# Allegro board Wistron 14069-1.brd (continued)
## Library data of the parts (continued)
PT4702 PT4707-PT4709 PT4802 PT4807 PT5004 PT5101 PT5201 = ECAP-138D8-UH355: tolerance: 09.2771D.C8L
PU51 = DFN10G3-G265175H32: tolerance: 74.08068.A43
PU4002 PU4003 U401-U404 U3102 = SOT23DGS2D4H44: tolerance: 84.2N702.X31
PU4601 = WQFN56J6-G4D75H32: tolerance: 074.03607.0073
PU4701-PU4704 PU4708 PU4712 PU4718 PU4721 PU4802 PU4803 PU4807 PU4808 PU5003 PU5102 PU5203 PU5302 = PPAK-8PH48: tolerance: 084.04378.0037
PU4705-PU4707 PU4710 PU4711 PU4714 PU4715 PU4717 PU4801 PU4805 PU4806 PU4810 PU5001 PU5103 PU5201 PU5303 = PPAK-8PH48: tolerance: 084.04504.0037
PU4709 PU4713 PU4716 PU4719 PU4804 PU4809 = DFN8F3-G2416H32: tolerance: 074.09624.0BE3
PU5002 = QFN20-G1D75H32: tolerance: 74.08207.C73
PU5101 PU5301 = DFN10G3-G265175H32: tolerance: 74.08237.B73
PU5202 = QFN16G3-G1D85-UH40: tolerance: 74.05230.073
Q1 = SOT-363H44: tolerance: 75.27002.D7C
Q2 = SOT23DGS2D8H50: tolerance: 84.03418.A31
Q23 Q25 = SOT-363H44: tolerance: 84.2N702.A3F
Q58 Q5701 = SOT23DGS2D4H44: tolerance: 84.2N702.J31
Q72 Q5702 U2 = SOT-363H44: tolerance: 75.03904.A7C
Q73 Q3515 = SOT23CBE2D4H44: tolerance: 84.T3904.C11
Q98 Q3401 Q3402 Q3512 Q3514 Q3516 Q3518 Q4301-Q4304 Q6401 Q6406 Q6805 Q6807 U5202 U5203 = SOT23DGS2D4H48: tolerance: 84.2N702.E31
Q2002 Q2601 Q2606 Q2903 Q3107 = SOT23CBE2D4H44: tolerance: 84.T3904.H11
Q2004 Q2007 = SOT23DGS2D4H44: tolerance: 84.27002.Z31
Q2005 Q2602-Q2605 Q2702-Q2705 Q6403 Q6405 Q6407 Q6806 = SOT23CBE2D4H44: tolerance: 84.T3906.A11
Q2901 Q2902 Q3001-Q3003 = SC70-6H48: tolerance: 84.01C03.01F
Q3103 = SOT-363H44: tolerance: 75.03904.B7C
Q3106 Q3109 = SOT23DGS2D8H50: tolerance: 84.03419.031
Q3507 = SMD-TO-252-DGS6698H99: tolerance: 84.03004.036
Q3508 Q3509 = SOT23DGS2D8H50: tolerance: 84.03413.B31
Q5601 Q5602 = SOT23DGS2D4H44: tolerance: 84.2N702.031
Q5603 = SOT-363H44: tolerance: 75.27002.B7C; signal model: 6pins2
Q5703 Q6402 U5 U25-U28 = SOT-363H44: tolerance: 75.27002.F7C
Q5704 = SOT-363H44: tolerance: 75.27002.F7C; signal model: 6pins2
Q5705 = SOT23DGS2D4H48: tolerance: 84.02130.031
Q6404 = SOT23DGS2D4H44: tolerance: 84.00138.F31
Q9303 U3402 = SOIC8H79: tolerance: 75.05003.071
R78 R531 R3158 = R402H16: tolerance: 63.47334.1DL
R80 R4308-R4310 R6824 R6825 = R805H24: tolerance: 63.22133.16L
R83 R2054 R2203 R2205 R2207 R2210 R2212 R2214 R2217 R2219 R2221 R2223 R2602 R2611 R2612 R2618 R2622 R2630 R2632 R2932 R2941 R2942 R2944 R5707 R6408 R6414 R6416 R6420 R6421 R6823 R7919 = R402H16: tolerance: 63.47234.1DL
R302 R703 R1123 R1207 = R402H16: tolerance: 64.24R95.6DL
R403 R407 R408 R2038 R2040 R2043 = R402H16: tolerance: 64.51R05.6DL
R404 R405 = R402H16: tolerance: 63.51034.1DL
R414 R416-R420 R423-R432 R458 R813 R814 R879 R1605 R1606 R1706 R1707 R2010 R2019 R2021 R2030 R2035 R2048 R2058 R2059 R2202 R2209 R2213 R2479 R2502-R2504 R2515 R2709 R2710 R2713 R2930 R2937-R2940 R2948-R2955 R3014-R3019 R3115 R3120 R3161 R3168 R3501 R5204 R5703 R7928 R7947-R7950 R7965-R7967 R9902-R9904 R9906 R9915 R9919 = R402H16: tolerance: 63.10234.1DL
R422 R702 = R402H16: tolerance: 63.20034.1DL
R469 = R402H16: tolerance: 63.22134.1DL
R470 = R402H16: tolerance: 64.56R05.6DL
R507 = R402H16: tolerance: 64.12405.6DL
R508 = R402H16: tolerance: 64.21005.6DL
R544 R1613 R1614 R2008 R2015 R2605 R2610 R2616 R2626 R2633 R3008 R3011 R5610-R5613 R5711 R5713 R9905 R9918 = R402H16: tolerance: 63.22234.1DL
R650 R704 R3103 R3514 R3515 R3519 R3520 R3917 = R603H22: tolerance: 63.00000.00L
R901 R1704 = R402H16: tolerance: 63.56134.1DL
R1009 = R402H16: tolerance: 63.33134.1DL
R1117-R1119 R1132 = R402H16: tolerance: 64.24005.6DL
R1126 R1206 = R402H16: tolerance: 64.2R005.6DL
R1129 R1130 R1204 R1205 R2002-R2005 = R402H16: tolerance: 64.10015.6DL
R1510 R1807 R5614 R5708 R5710 = R402H16: tolerance: 63.10534.1DL
R1521 R1705 R2106 R2130 = R402H16: tolerance: 63.30034.1DL
R1604 = R402H16: tolerance: 64.11305.6DL
R1803 = R402H16: tolerance: 64.27015.6DL
R1808 = R603H22: tolerance: 63.10633.15L
R1909-R1911 = R402H16: tolerance: 63.22034.1DL
R2006 R2009 = R603H22: tolerance: 63.75033.15L
R2016 R2018 = R402H16: tolerance: 64.49905.6DL
R2017 R2020 R2022 R2025 R2714 = R402H16: tolerance: 63.33034.1DL; signal model: 2pins
R2024 R2620 R2631 R3114 = R402H16: tolerance: 63.82234.1DL
R2028 R2029 R6108 R6214 R6404 R6418 R7922 R7924 R7939 R7951 = R402H16: tolerance: 63.33034.1DL
R2037 = R402H16: tolerance: 64.51R15.6DL
R2046 R2049 R2204 R2206 R2208 R2211 R2215 R2218 R2220 R2222 R2224 R2603 R2619 R2623 R5702 R7943 R31132 = R402H16: tolerance: 63.20334.1DL
R2053 = R402H16: tolerance: 64.47005.6DL
R2056 R2716 R2909 R2920 R2926 R3013 R3415 R4020 R5615 = R402H16: tolerance: 64.20025.6DL
R2227 = R402H16: tolerance: 63.15234.1DL
R2475 = R402H16: tolerance: 64.43R25.6DL
R2505-R2508 R2510 = R402H16: tolerance: 64.15R05.6DL; signal model: 2pins
R2511 R3412 R3413 = R402H16: tolerance: 63.R0034.1DL; signal model: 2pins
R2514 = R402H16: tolerance: 64.15015.6DL
R2516 = R402H16: tolerance: 64.45325.6DL
R2617 R2624 = R402H16: tolerance: 64.33005.6DL
R2712 = R402H16: tolerance: 63.22434.1DL
R2907 = R402H16: tolerance: 64.39225.6DL
R2943 R2946 R3006 R3007 R6406 R6407 R6412 R6413 R6821 R6822 = R402H16: tolerance: 63.22334.1DL
R2945 R2947 R3002-R3005 R3009 R3010 = R402H16: tolerance: 63.75034.1DL
R3012 = R402H16: tolerance: 64.51015.6DL
R3102 = R402H16: tolerance: 64.24915.6DL
R3111 = R402H16: tolerance: 63.10634.1DL
R3113 = R402H16: tolerance: 64.20015.6DL
R3118 = R402H16: tolerance: 63.15334.1DL
R3163 = R402H16: tolerance: 63.39434.1DL
R3204-R3206 = R603H22: tolerance: 63.33133.15L
R3417 = R402H16: tolerance: 64.46425.6DL
R3523 = R402H16: tolerance: 63.27234.1DL
R3604 R3702 R3704 R3706 R3816 R3919 R5705 = R402H16: tolerance: 64.15025.6DL
R4018 = R402H16: tolerance: 64.47025.6DL
R5602-R5609 = R402H16: tolerance: 63.47134.1DL
R5709 = R402H16: tolerance: 64.49915.6DL
R6402 = R603H22: tolerance: 63.68033.15L
R6410 R6415 R6417 = R805H24: tolerance: 63.75031.16L
R6424 = R603H22: tolerance: 64.16505.55L
R6426 R6427 = R603H22: tolerance: 64.75R05.55L
R7952 = R402H16: tolerance: 64.56025.6DL
R7958 = R402H16: tolerance: 64.64915.6DL
R7963 R7968 = R402H16: tolerance: 64.17825.6DL
R9913 = R402H16: tolerance: 64.15005.6DL
R64013 = R805H24: tolerance: 63.13131.16L
RN7901 RN7902 RN7905 RN7909 = SMD-ARES4-2H18-U: tolerance: 66.1033A.04L
RT2402 RT2403 = NTC-402H22-U: tolerance: 69.60011.121
SATA2 SATA3 = ABA-SAT-054-K02: tolerance: 20.81443.007
SATA4 SATA5 = T12-0047-1A30-0: tolerance: 20.81593.007
SATAEX1 = ASAT0008-P001C01: tolerance: 020.80289.0018
SIO1 = PQFP128H134: tolerance: 71.08732.A0E
SPI1 = SKT-SOIC8-092117H235: tolerance: 62.10089.001
SPK1 = P125-2204P-A1BS-025-U: tolerance: 21.63415.204
TC5 = CT3528H48: tolerance: 77.C4761.041
TC2601 TC2602 TC3401 TC3601 TC3701 TC3702 TC3801 TC3802 TC3901 TC9302 TC9401 TC9402 = ECAP-100D6D3H473: tolerance: 09.2271D.X8L
TC2903 TC2904 TC3001 TC3004 = ECAP-100D5H573: tolerance: 09.1071D.0IL
TP168 = TPAD28-1-U: tolerance: ZZ.00PAD.1F1
TP_3G16_JTAG5 TP_3G16_RSVD_A1-TP_3G16_RSVD_A3 TP_3G16RSVD_A1 TP_3G18_RSVD_B1 TP_16PRSNT_B1 TP_CPU1-TP_CPU4 TP_CPU7 TP_CPU9-TP_CPU13 TP_CPU_AC40 TP_CPU_AV1 TP_CPU_AV39 TP_CPU_AW2 TP_CPU_AW38 TP_CPU_G14 TP_CPU_H11 TP_CPU_H12 TP_CPU_H14 TP_CPU_J7 TP_CPU_J8 TP_CPU_K8 TP_CPU_K12 TP_CPU_L8 TP_CPU_L12 TP_DIMM_12V TP_DIMM_12V1-TP_DIMM_12V7 TP_PCH_AB13 TP_PCH_AN17 TP_PCH_AN29 TP_PCH_AR17 TP_PCH_AR19 TP_PCH_AR22 TP_PCH_AW42 TP_PCH_AW45 TP_PCH_BD14 TP_PCH_N29 TP_PCH_N31 TP_PCH_N45 TP_PCH_P24 TP_PCH_P27 TP_PCH_P29 TP_PCH_P31 TP_PCH_R24 TP_PCH_R27 TP_PCH_U13 TP_PCH_W13 TP_SET1-TP_SET8 = TPAD24: tolerance: ZZ.PAD24.001
TP_CPU_AB37 TP_CPU_AC37 TP_CPU_AC38 TP_CPU_D14 TP_LAN_PIN25-TP_LAN_PIN27 TP_PCH_AN43 TP_PCH_AN44 TP_PCH_AR39 TP_PCH_AR45 TP_PCH_BC1 TP_SLP_S5 TP_SUS_WARNB TP_SUSACK_N TP_VBAT_1 TP_VBAT_2 = TPAD28: tolerance: ZZ.PAD28.XXX
TR5701-TR5704 = L125100-4PH24: tolerance: 68.24121.201; signal model: 4pins2
U2RJ1 = RU1-AQ1K9WGF: tolerance: 22.10321.V61
U16 = SMD-TO-252-4H94: tolerance: 74.01085.U3A
U62 U63 = SC70-5H44: tolerance: 73.01G08.DHG
U2501 = SOIC8-1H86: tolerance: 72.25647.00A
U2701 = LQFP48H63: tolerance: 71.00662.A0G
U3101 = QFN32J4-G2D85H36: tolerance: 71.08111.Y03
U3401 = QFN16-G1D8-UH32: tolerance: 74.02540.A73
U3601 U3603 U3604 U3607 = SOT23-8PH36: tolerance: 74.07605.079
U3605 U3606 U3608 = SOT-23-5H56: tolerance: 74.06288.07F
U4002 = QFN12J1D6H24: tolerance: 074.74375.0073
U7902 = SOIC8H69: tolerance: 72.25106.001
USB2F2 = A2541WV0-2AX5PA-6T-K: tolerance: 21.62870.205
USB3F1 = ABA-USB-050-K07: tolerance: 21.62836.210
USB3R1 USB3R2 = SKT-USB22-156174: tolerance: 22.10339.771
WPWR1 = A2008WV0-2P: tolerance: 21.61337.102
X1801 = SMD49-6914-0403H56: tolerance: 82.30001.661
X1802 = OSC-3225-4P-4H36: tolerance: 082.30006.0021
X3101 = OSC-3225-4P-4H36: tolerance: 82.30020.G71
XDP1 = DM-BSH-03001-FDA-01: tolerance: ZZ.F0441.06001

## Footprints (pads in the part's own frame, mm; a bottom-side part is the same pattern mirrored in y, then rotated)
0R0402-PAD-1
  custom 0.14x0.14 smd: 1(0,0.445) 2(0,-0.445)
0R0603-PAD-1-U
  custom 0.216x0.216 smd: 1(0,0.762) 2(0,-0.762)
0R0805-PAD-1-U
  rect 1.397x1.562 smd: 1(0,0.965)
  rect 1.397x1.569 smd: 2(0,-0.965)
1E450400
  round 1.422 hole 1.016: 1(5.08,-1.27) 2(5.08,1.27) 3(2.54,-1.27) 4(2.54,1.27) 5(0,-1.27) 6(0,1.27) 8(-2.54,1.27) 9(-5.08,-1.27) 10(-5.08,1.27)
  rect 0.025x0.025 smd: 7(-2.54,-1.27)
4-1470780-7
  round 0.254 hole 2.362 unplated: (0,0) (73.149,0)
  round 1.092 hole 0.737: A1(-11.65,1.25) A2(-10.65,3.25) A3(-9.649,1.25) A4(-8.65,3.25) A5(-7.65,1.25) A6(-6.65,3.25) A7(-5.65,1.25) A8(-4.649,3.25) A9(-3.65,1.25) A10(-2.65,3.25) A11(-1.65,1.25) A12(1.35,3.25) A13(2.349,1.25) A14(3.35,3.25) A15(4.35,1.25) A16(5.351,3.25) A17(6.35,1.25) A18(7.349,3.25) A19(8.35,1.25) A20(9.35,3.25) A21(10.351,1.25) A22(11.35,3.25) A23(12.349,1.25) A24(13.35,3.25) A25(14.35,1.25) A26(15.35,3.25) A27(16.35,1.25) A28(17.349,3.25) A29(18.35,1.25) A30(19.35,3.25) A31(20.35,1.25) A32(21.35,3.25) A33(22.349,1.25) A34(23.35,3.25) A35(24.35,1.25) A36(25.35,3.25) A37(26.35,1.25) A38(27.349,3.25) A39(28.35,1.25) A40(29.35,3.25) A41(30.35,1.25) A42(31.35,3.25) A43(32.349,1.25) A44(33.35,3.25) A45(34.35,1.25) A46(35.35,3.25) A47(36.35,1.25) A48(37.349,3.25) A49(38.35,1.25) A50(39.35,3.25) A51(40.35,1.25) A52(41.35,3.25) A53(42.349,1.25) A54(43.35,3.25) A55(44.35,1.25) A56(45.35,3.25) A57(46.35,1.25) A58(47.349,3.25) A59(48.35,1.25) A60(49.35,3.25) A61(50.35,1.25) A62(51.35,3.25) A63(52.349,1.25) A64(53.35,3.25) A65(54.35,1.25) A66(55.35,3.25) A67(56.35,1.25) A68(57.349,3.25) A69(58.35,1.25) A70(59.35,3.25) A71(60.35,1.25) A72(61.35,3.25) A73(62.349,1.25) A74(63.35,3.25) A75(64.35,1.25) A76(65.35,3.25) A77(66.35,1.25) A78(67.349,3.25) A79(68.35,1.25) A80(69.35,3.25) A81(70.35,1.25) A82(71.35,3.25) B1(-11.65,-1.25) B2(-10.65,-3.25) B3(-9.649,-1.25) B4(-8.65,-3.25) B5(-7.65,-1.25) B6(-6.65,-3.25) B7(-5.65,-1.25) B8(-4.649,-3.25) B9(-3.65,-1.25) B10(-2.65,-3.25) B11(-1.65,-1.25) B12(1.35,-3.25) B13(2.349,-1.25) B14(3.35,-3.25) B15(4.35,-1.25) B16(5.351,-3.25) B17(6.35,-1.25) B18(7.349,-3.25) B19(8.35,-1.25) B20(9.35,-3.25) B21(10.351,-1.25) B22(11.35,-3.25) B23(12.349,-1.25) B24(13.35,-3.25) B25(14.35,-1.25) B26(15.35,-3.25) B27(16.35,-1.25) B28(17.349,-3.25) B29(18.35,-1.25) B30(19.35,-3.25) B31(20.35,-1.25) B32(21.35,-3.25) B33(22.349,-1.25) B34(23.35,-3.25) B35(24.35,-1.25) B36(25.35,-3.25) B37(26.35,-1.25) B38(27.349,-3.25) B39(28.35,-1.25) B40(29.35,-3.25) B41(30.35,-1.25) B42(31.35,-3.25) B43(32.349,-1.25) B44(33.35,-3.25) B45(34.35,-1.25) B46(35.35,-3.25) B47(36.35,-1.25) B48(37.349,-3.25) B49(38.35,-1.25) B50(39.35,-3.25) B51(40.35,-1.25) B52(41.35,-3.25) B53(42.349,-1.25) B54(43.35,-3.25) B55(44.35,-1.25) B56(45.35,-3.25) B57(46.35,-1.25) B58(47.349,-3.25) B59(48.35,-1.25) B60(49.35,-3.25) B61(50.35,-1.25) B62(51.35,-3.25) B63(52.349,-1.25) B64(53.35,-3.25) B65(54.35,-1.25) B66(55.35,-3.25) B67(56.35,-1.25) B68(57.349,-3.25) B69(58.35,-1.25) B70(59.35,-3.25) B71(60.35,-1.25) B72(61.35,-3.25) B73(62.349,-1.25) B74(63.35,-3.25) B75(64.35,-1.25) B76(65.35,-3.25) B77(66.35,-1.25) B78(67.349,-3.25) B79(68.35,-1.25) B80(69.35,-3.25) B81(70.35,-1.25) B82(71.35,-3.25)
21S-91-03GB01
  round 1.422 hole 1.016: 1(-2.54,0) 2(0,0) 3(2.54,0)
210-91-05GY21-U
  rect 0.025x0.025 smd: 1(-5.08,0)
  round 1.422 hole 1.016: 2(-2.54,0) 3(0,0) 4(2.54,0) 5(5.08,0)
210-92-07GB11
  rect 0.025x0.025 smd: 1(-7.62,-1.27)
  round 1.422 hole 1.016: 2(-7.62,1.27) 3(-5.08,-1.27) 4(-5.08,1.27) 5(-2.54,-1.27) 6(-2.54,1.27) 7(0,-1.27) 8(0,1.27) 9(2.54,-1.27) 10(2.54,1.27) 11(5.08,-1.27) 12(5.08,1.27) 13(7.62,-1.27) 14(7.62,1.27)
220-47-07GB22
  round 1.27 hole 0.889: 1(-6,-1) 2(-6,1) 3(-4,-1) 4(-4,1) 6(-2,1) 7(0,-1) 8(0,1) 9(2,-1) 10(2,1) 11(4,-1) 12(4,1) 13(6,-1) 14(6,1)
  rect 0.025x0.025 smd: 5(-2,-1)
105020-0001
  round 0.762 hole 0.406: 1(6.36,6.88) 2(5,5.88) 3(5.36,6.88) 4(4,5.88) 5(4.36,6.88) 6(3,5.88) 7(2.51,6.88) 8(2,5.88) 9(1.51,6.88) 10(1,5.88) 11(-0.35,6.88) 12(0,5.88) 13(-1.35,6.88) 14(-1,5.88) 15(-2.35,6.88) 16(-2,5.88) 17(-3.35,6.88) 18(-3,5.88) 19(-4.35,6.88) 20(-4,5.88)
  oval 1.321x2.921 hole 0.61x2.21: X1(8.25,6.48) X3(-8.25,6.48)
  oval 1.321x2.413 hole 0.61x1.702: X2(8.25,0) X4(-8.25,0)
A2008WV0-2P
  round 1.27 hole 0.889: 1(1,0) 2(-1,0)
A2541WV0-1EX2PA-6T
  round 1.397 hole 0.991: 1(-1.27,0) 2(1.27,0)
A2541WV0-2AX5PA-6T-K
  rect 0.025x0.025 smd: 1(5.08,-1.27)
  round 1.422 hole 1.016: 2(5.08,1.27) 3(2.54,-1.27) 4(2.54,1.27) 5(0,-1.27) 6(0,1.27) 7(-2.54,-1.27) 8(-2.54,1.27) 9(-5.08,-1.27) 10(-5.08,1.27)
A2543WV2-3P
  round 1.422 hole 1.016: 1(2.54,0) 2(0,0) 3(-2.54,0)
AAA-BAT-029-K01
  round 1.727 hole 1.321: 1(11.8,0) 2(-8.2,0)
AAA-PCI-003-K45
  round 0.254 hole 2.362 unplated: (0,0) (9.15,0)
  round 1.092 hole 0.737: A1(-11.65,1.25) A2(-10.65,3.25) A3(-9.65,1.25) A4(-8.65,3.25) A5(-7.65,1.25) A6(-6.65,3.25) A7(-5.65,1.25) A8(-4.65,3.25) A9(-3.65,1.25) A10(-2.65,3.25) A11(-1.65,1.25) A12(1.35,3.25) A13(2.35,1.25) A14(3.35,3.25) A15(4.35,1.25) A16(5.35,3.25) A17(6.35,1.25) A18(7.35,3.25) B1(-11.65,-1.25) B2(-10.65,-3.25) B3(-9.65,-1.25) B4(-8.65,-3.25) B5(-7.65,-1.25) B6(-6.65,-3.25) B7(-5.65,-1.25) B8(-4.65,-3.25) B9(-3.65,-1.25) B10(-2.65,-3.25) B11(-1.65,-1.25) B12(1.35,-3.25) B13(2.35,-1.25) B14(3.35,-3.25) B15(4.35,-1.25) B16(5.35,-3.25) B17(6.35,-1.25) B18(7.35,-3.25)
ABA-JAK-028-K03
  round 0.254 hole 2.311 unplated: (0,0)
  round 1.422 hole 1.016: 1(0,-3.8) 2(-5,-3.8) 3(-2.5,-3.8) 4(2.5,-3.8) 5(5,-3.8) 22(-3.75,-8.8) 23(-1.25,-8.8) 24(1.25,-8.8) 25(3.75,-8.8) 32(-3.75,-13.8) 33(-1.25,-13.8) 34(1.25,-13.8) 35(3.75,-13.8)
  round 2.718 hole 2.311: G1(6.04,0) G2(-6.04,0) G3(6.04,-11.3) G4(-6.04,-11.3)
ABA-SAT-054-K02
  round 0.991 hole 0.635: 1(3.81,0) 2(2.755,1.5) 3(1.055,1.5) 4(0,0) 5(-1.055,1.5) 6(-2.755,1.5) 7(-3.81,0)
  round 1.778 hole 1.372: 8(6.27,0) 9(-6.56,1)
ABA-USB-050-K07
  round 1.168 hole 0.813: 1(-9,1) 2(-7,1) 3(-5,1) 4(-3,1) 5(-1,1) 6(1,1) 7(3,1) 8(5,1) 9(7,1) 10(9,1) 11(9,-1) 12(7,-1) 13(5,-1) 14(3,-1) 15(1,-1) 16(-1,-1) 17(-3,-1) 18(-5,-1) 19(-7,-1)
  rect 0.025x0.025 smd: 20(-9,-1)
AH08847-A9L2-4M
  round 0.254 hole 2.464 unplated: (-74.55,0) (63.4,0)
  round 0.254 hole 2.464x1.219 unplated: (0,0)
  round 1.016 hole 0.66: 1(-68.9,-2.7) 2(-68.05,-1.1) 3(-67.2,-2.7) 4(-66.35,-1.1) 5(-65.5,-2.7) 6(-64.65,-1.1) 7(-63.8,-2.7) 8(-62.95,-1.1) 9(-62.1,-2.7) 10(-61.25,-1.1) 11(-60.4,-2.7) 12(-59.55,-1.1) 13(-58.7,-2.7) 14(-57.85,-1.1) 15(-57,-2.7) 16(-56.15,-1.1) 17(-55.3,-2.7) 18(-54.45,-1.1) 19(-53.6,-2.7) 20(-52.75,-1.1) 21(-51.9,-2.7) 22(-51.05,-1.1) 23(-50.2,-2.7) 24(-49.35,-1.1) 25(-48.5,-2.7) 26(-47.65,-1.1) 27(-46.8,-2.7) 28(-45.95,-1.1) 29(-45.1,-2.7) 30(-44.25,-1.1) 31(-43.4,-2.7) 32(-42.55,-1.1) 33(-41.7,-2.7) 34(-40.85,-1.1) 35(-40,-2.7) 36(-39.15,-1.1) 37(-38.3,-2.7) 38(-37.45,-1.1) 39(-36.6,-2.7) 40(-35.75,-1.1) 41(-34.9,-2.7) 42(-34.05,-1.1) 43(-33.2,-2.7) 44(-32.35,-1.1) 45(-31.5,-2.7) 46(-30.65,-1.1) 47(-29.8,-2.7) 48(-28.95,-1.1) 49(-28.1,-2.7) 50(-27.25,-1.1) 51(-26.4,-2.7) 52(-25.55,-1.1) 53(-24.7,-2.7) 54(-23.85,-1.1) 55(-23,-2.7) 56(-22.15,-1.1) 57(-21.3,-2.7) 58(-20.45,-1.1) 59(-19.6,-2.7) 60(-18.75,-1.1) 61(-17.9,-2.7) 62(-17.05,-1.1) 63(-16.2,-2.7) 64(-15.35,-1.1) 65(-14.5,-2.7) 66(-13.65,-1.1) 67(-12.8,-2.7) 68(-11.95,-1.1) 69(-11.1,-2.7) 70(-10.25,-1.1) 71(-9.4,-2.7) 72(-8.55,-1.1) 73(-7.7,-2.7) 74(-6.85,-1.1) 75(-6,-2.7) 76(-5.15,-1.1) 77(-4.3,-2.7) 78(1.65,-1.1) 79(2.5,-2.7) 80(3.35,-1.1) 81(4.2,-2.7) 82(5.05,-1.1) 83(5.9,-2.7) 84(6.75,-1.1) 85(7.6,-2.7) 86(8.45,-1.1) 87(9.3,-2.7) 88(10.15,-1.1) 89(11,-2.7) 90(11.85,-1.1) 91(12.7,-2.7) 92(13.55,-1.1) 93(14.4,-2.7) 94(15.25,-1.1) 95(16.1,-2.7) 96(16.95,-1.1) 97(17.8,-2.7) 98(18.65,-1.1) 99(19.5,-2.7) 100(20.35,-1.1) 101(21.2,-2.7) 102(22.05,-1.1) 103(22.9,-2.7) 104(23.75,-1.1) 105(24.6,-2.7) 106(25.45,-1.1) 107(26.3,-2.7) 108(27.15,-1.1) 109(28,-2.7) 110(28.85,-1.1) 111(29.7,-2.7) 112(30.55,-1.1) 113(31.4,-2.7) 114(32.25,-1.1) 115(33.1,-2.7) 116(33.95,-1.1) 117(34.8,-2.7) 118(35.65,-1.1) 119(36.5,-2.7) 120(37.35,-1.1) 121(38.2,-2.7) 122(39.05,-1.1) 123(39.9,-2.7) 124(40.75,-1.1) 125(41.6,-2.7) 126(42.45,-1.1) 127(43.3,-2.7) 128(44.15,-1.1) 129(45,-2.7) 130(45.85,-1.1) 131(46.7,-2.7) 132(47.55,-1.1) 133(48.4,-2.7) 134(49.25,-1.1) 135(50.1,-2.7) 136(50.95,-1.1) 137(51.8,-2.7) 138(52.65,-1.1) 139(53.5,-2.7) 140(54.35,-1.1) 141(55.2,-2.7) 142(56.05,-1.1) 143(56.9,-2.7) 144(57.75,-1.1) 145(-68.9,1.1) 146(-68.05,2.7) 147(-67.2,1.1) 148(-66.35,2.7) 149(-65.5,1.1) 150(-64.65,2.7) 151(-63.8,1.1) 152(-62.95,2.7) 153(-62.1,1.1) 154(-61.25,2.7) 155(-60.4,1.1) 156(-59.55,2.7) 157(-58.7,1.1) 158(-57.85,2.7) 159(-57,1.1) 160(-56.15,2.7) 161(-55.3,1.1) 162(-54.45,2.7) 163(-53.6,1.1) 164(-52.75,2.7) 165(-51.9,1.1) 166(-51.05,2.7) 167(-50.2,1.1) 168(-49.35,2.7) 169(-48.5,1.1) 170(-47.65,2.7) 171(-46.8,1.1) 172(-45.95,2.7) 173(-45.1,1.1) 174(-44.25,2.7) 175(-43.4,1.1) 176(-42.55,2.7) 177(-41.7,1.1) 178(-40.85,2.7) 179(-40,1.1) 180(-39.15,2.7) 181(-38.3,1.1) 182(-37.45,2.7) 183(-36.6,1.1) 184(-35.75,2.7) 185(-34.9,1.1) 186(-34.05,2.7) 187(-33.2,1.1) 188(-32.35,2.7) 189(-31.5,1.1) 190(-30.65,2.7) 191(-29.8,1.1) 192(-28.95,2.7) 193(-28.1,1.1) 194(-27.25,2.7) 195(-26.4,1.1) 196(-25.55,2.7) 197(-24.7,1.1) 198(-23.85,2.7) 199(-23,1.1) 200(-22.15,2.7) 201(-21.3,1.1) 202(-20.45,2.7) 203(-19.6,1.1) 204(-18.75,2.7) 205(-17.9,1.1) 206(-17.05,2.7) 207(-16.2,1.1) 208(-15.35,2.7) 209(-14.5,1.1) 210(-13.65,2.7) 211(-12.8,1.1) 212(-11.95,2.7) 213(-11.1,1.1) 214(-10.25,2.7) 215(-9.4,1.1) 216(-8.55,2.7) 217(-7.7,1.1) 218(-6.85,2.7) 219(-6,1.1) 220(-5.15,2.7) 221(-4.3,1.1) 222(1.65,2.7) 223(2.5,1.1) 224(3.35,2.7) 225(4.2,1.1) 226(5.05,2.7) 227(5.9,1.1) 228(6.75,2.7) 229(7.6,1.1) 230(8.45,2.7) 231(9.3,1.1) 232(10.15,2.7) 233(11,1.1) 234(11.85,2.7) 235(12.7,1.1) 236(13.55,2.7) 237(14.4,1.1) 238(15.25,2.7) 239(16.1,1.1) 240(16.95,2.7) 241(17.8,1.1) 242(18.65,2.7) 243(19.5,1.1) 244(20.35,2.7) 245(21.2,1.1) 246(22.05,2.7) 247(22.9,1.1) 248(23.75,2.7) 249(24.6,1.1) 250(25.45,2.7) 251(26.3,1.1) 252(27.15,2.7) 253(28,1.1) 254(28.85,2.7) 255(29.7,1.1) 256(30.55,2.7) 257(31.4,1.1) 258(32.25,2.7) 259(33.1,1.1) 260(33.95,2.7) 261(34.8,1.1) 262(35.65,2.7) 263(36.5,1.1) 264(37.35,2.7) 265(38.2,1.1) 266(39.05,2.7) 267(39.9,1.1) 268(40.75,2.7) 269(41.6,1.1) 270(42.45,2.7) 271(43.3,1.1) 272(44.15,2.7) 273(45,1.1) 274(45.85,2.7) 275(46.7,1.1) 276(47.55,2.7) 277(48.4,1.1) 278(49.25,2.7) 279(50.1,1.1) 280(50.95,2.7) 281(51.8,1.1) 282(52.65,2.7) 283(53.5,1.1) 284(54.35,2.7) 285(55.2,1.1) 286(56.05,2.7) 287(56.9,1.1) 288(57.75,2.7)
AS0BC21-S40BE-7H
  round 0.254 hole 1.168 unplated: (-10,0)
  round 0.254 hole 1.651 unplated: (10,0)
  rect 0.305x1.549 smd: 1(-9.25,5.275) 2(-9,-2.275) 3(-8.75,5.275) 4(-8.5,-2.275) 5(-8.25,5.275) 6(-8,-2.275) 7(-7.75,5.275) 8(-7.5,-2.275) 9(-7.25,5.275) 10(-7,-2.275) 11(-6.75,5.275) 12(-6.5,-2.275) 13(-6.25,5.275) 14(-6,-2.275) 15(-5.75,5.275) 16(-5.5,-2.275) 17(-5.25,5.275) 18(-5,-2.275) 19(-4.75,5.275) 20(-4.5,-2.275) 21(-4.25,5.275) 22(-4,-2.275) 23(-3.75,5.275) 32(-1.5,-2.275) 33(-1.25,5.275) 34(-1,-2.275) 35(-0.75,5.275) 36(-0.5,-2.275) 37(-0.25,5.275) 38(0,-2.275) 39(0.25,5.275) 40(0.5,-2.275) 41(0.75,5.275) 42(1,-2.275) 43(1.25,5.275) 44(1.5,-2.275) 45(1.75,5.275) 46(2,-2.275) 47(2.25,5.275) 48(2.5,-2.275) 49(2.75,5.275) 50(3,-2.275) 51(3.25,5.275) 52(3.5,-2.275) 53(3.75,5.275) 54(4,-2.275) 55(4.25,5.275) 56(4.5,-2.275) 57(4.75,5.275) 58(5,-2.275) 59(5.25,5.275) 60(5.5,-2.275) 61(5.75,5.275) 62(6,-2.275) 63(6.25,5.275) 64(6.5,-2.275) 65(6.75,5.275) 66(7,-2.275) 67(7.25,5.275) 68(7.5,-2.275) 69(7.75,5.275) 70(8,-2.275) 71(8.25,5.275) 72(8.5,-2.275) 73(8.75,5.275) 74(9,-2.275) 75(9.25,5.275)
  rect 1.194x2.743 smd: 76(-10.35,4.5) 77(10.35,4.5)
AS0BC21-S85BM-7H
  round 0.254 hole 1.168 unplated: (-10,0)
  round 0.254 hole 1.651 unplated: (10,0)
  rect 0.305x1.549 smd: 1(-9.25,4.725) 2(-9,-1.725) 3(-8.75,4.725) 4(-8.5,-1.725) 5(-8.25,4.725) 6(-8,-1.725) 7(-7.75,4.725) 8(-7.5,-1.725) 9(-7.25,4.725) 10(-7,-1.725) 11(-6.75,4.725) 12(-6.5,-1.725) 13(-6.25,4.725) 14(-6,-1.725) 15(-5.75,4.725) 16(-5.5,-1.725) 17(-5.25,4.725) 18(-5,-1.725) 19(-4.75,4.725) 20(-4.5,-1.725) 21(-4.25,4.725) 22(-4,-1.725) 23(-3.75,4.725) 24(-3.5,-1.725) 25(-3.25,4.725) 26(-3,-1.725) 27(-2.75,4.725) 28(-2.5,-1.725) 29(-2.25,4.725) 30(-2,-1.725) 31(-1.75,4.725) 32(-1.5,-1.725) 33(-1.25,4.725) 34(-1,-1.725) 35(-0.75,4.725) 36(-0.5,-1.725) 37(-0.25,4.725) 38(0,-1.725) 39(0.25,4.725) 40(0.5,-1.725) 41(0.75,4.725) 42(1,-1.725) 43(1.25,4.725) 44(1.5,-1.725) 45(1.75,4.725) 46(2,-1.725) 47(2.25,4.725) 48(2.5,-1.725) 49(2.75,4.725) 50(3,-1.725) 51(3.25,4.725) 52(3.5,-1.725) 53(3.75,4.725) 54(4,-1.725) 55(4.25,4.725) 56(4.5,-1.725) 57(4.75,4.725) 58(5,-1.725) 67(7.25,4.725) 68(7.5,-1.725) 69(7.75,4.725) 70(8,-1.725) 71(8.25,4.725) 72(8.5,-1.725) 73(8.75,4.725) 74(9,-1.725) 75(9.25,4.725)
  rect 1.194x2.743 smd: 76(-10.35,4.5) 77(10.35,4.5)
ASAT0008-P001C01
  round 1.778 hole 1.372: 19(22.27,0) 20(-17.6,1)
  oval 1.041x1.168 hole 0.762: P1(-12.19,0) P2(-13.46,0) P3(-14.73,0) P4(-16,0)
  round 1.118 hole 0.762: S1(19.81,0) S2(18.755,1.5) S3(17.055,1.5) S4(16,0) S5(14.945,1.5) S6(13.245,1.5) S7(12.19,0) S8(3.81,0) S9(2.755,1.5) S10(1.055,1.5) S11(0,0) S12(-1.055,1.5) S13(-2.755,1.5) S14(-3.81,0)
BGA837M23-1H58
  round 0.305 smd: A2(10.46,-10.814) A3(9.959,-10.814) A4(9.459,-10.814) A42(-9.459,-10.814) A43(-9.959,-10.814) A44(-10.46,-10.814) AA17(3.099,-0.775) AA18(2.324,-0.775) AA20(1.549,-0.775) AA21(0.775,-0.775) AA23(0,-0.775) AA25(-0.775,-0.775) AA26(-1.549,-0.775) AA28(-2.324,-0.775) AA29(-3.099,-0.775) AB7(8.175,-0.667) AB8(7.413,-0.667) AB10(6.651,-0.667) AB11(5.889,-0.667) AB13(5.127,-0.667) AB14(4.365,-0.667) AB15(3.807,-0.667) AB31(-3.807,-0.667) AB32(-4.365,-0.667) AB33(-5.127,-0.667) AB35(-5.889,-0.667) AB36(-6.651,-0.667) AB38(-7.413,-0.667) AB39(-8.175,-0.667) AC17(3.099,0) AC18(2.324,0) AC20(1.549,0) AC21(0.775,0) AC23(0,0) AC25(-0.775,0) AC26(-1.549,0) AC28(-2.324,0) AC29(-3.099,0) AD7(8.175,0.667) AD8(7.413,0.667) AD10(6.651,0.667) AD11(5.889,0.667) AD13(5.127,0.667) AD14(4.365,0.667) AD15(3.807,0.667) AD31(-3.807,0.667) AD32(-4.365,0.667) AD33(-5.127,0.667) AD35(-5.889,0.667) AD36(-6.651,0.667) AD38(-7.413,0.667) AD39(-8.175,0.667) AE17(3.099,0.775) AE18(2.324,0.775) AE20(1.549,0.775) AE21(0.775,0.775) AE23(0,0.775) AE25(-0.775,0.775) AE26(-1.549,0.775) AE28(-2.324,0.775) AE29(-3.099,0.775) AF17(3.099,1.549) AF18(2.324,1.549) AF20(1.549,1.549) AF21(0.775,1.549) AF23(0,1.549) AF25(-0.775,1.549) AF26(-1.549,1.549) AF28(-2.324,1.549) AF29(-3.099,1.549) AG7(8.175,1.772) AG8(7.413,1.772) AG10(6.651,1.772) AG11(5.889,1.772) AG13(5.127,1.772) AG14(4.365,1.772) AG15(3.807,1.772) AG31(-3.807,1.772) AG32(-4.365,1.772) AG33(-5.127,1.772) AG35(-5.889,1.772) AG36(-6.651,1.772) AG38(-7.413,1.772) AG39(-8.175,1.772) AH17(3.099,2.324) AH18(2.324,2.324) AH20(1.549,2.324) AH21(0.775,2.324) AH23(0,2.324) AH25(-0.775,2.324) AH26(-1.549,2.324) AH28(-2.324,2.324) AH29(-3.099,2.324) AJ7(8.074,2.953) AJ8(7.312,2.953) AJ10(6.55,2.953) AJ11(5.788,2.953) AJ13(5.026,2.953) AJ14(4.315,2.953) AJ15(3.807,2.953) AJ17(3.099,3.099) AJ18(2.324,3.099) AJ20(1.549,3.099) AJ21(0.775,3.099) AJ23(0,3.099) AJ25(-0.775,3.099) AJ26(-1.549,3.099) AJ28(-2.324,3.099) AJ29(-3.099,3.099) AJ31(-3.807,2.953) AJ32(-4.365,2.953) AJ33(-5.127,2.953) AJ35(-5.889,2.953) AJ36(-6.651,2.953) AJ38(-7.413,2.953) AJ39(-8.175,2.953) AL7(8.074,4.071) AL8(7.312,4.071) AL10(6.55,4.071) AL11(5.788,4.071) AL13(5.026,4.071) AL17(2.953,3.807) AL19(1.772,3.807) AL22(0.667,3.807) AL24(-0.667,3.807) AL27(-1.772,3.807) AL29(-2.953,3.807) AL32(-4.34,4.096) AL33(-5.102,4.096) AL35(-5.864,4.096) AL36(-6.626,4.096) AL38(-7.388,4.096) AL39(-8.15,4.096) AM15(4.096,4.34) AM17(2.953,4.365) AM19(1.772,4.365) AM22(0.667,4.365) AM24(-0.667,4.365) AM27(-1.772,4.365) AM29(-2.953,4.315) AN7(8.023,5.036) AN8(7.261,4.985) AN10(6.499,4.985) AN11(5.753,5.026) AN15(4.096,5.102) AN17(2.953,5.127) AN19(1.772,5.127) AN22(0.667,5.127) AN24(-0.667,5.127) AN27(-1.772,5.127) AN29(-2.953,5.026) AN31(-4.071,5.026) AN36(-6.47,5.087) AN38(-7.232,5.087) AN39(-7.994,5.087) AP11(6.04,5.551) AR7(7.999,6.037) AR9(7.084,6.077) AR15(4.096,5.864) AR17(2.953,5.889) AR19(1.772,5.889) AR22(0.667,5.889) AR24(-0.667,5.889) AR27(-1.772,5.889) AR29(-2.953,5.788) AR31(-4.071,5.788) AR33(-5.026,5.753) AR34(-5.551,6.04) AR38(-7.396,6.068) AR39(-8.158,6.068) AT9(6.938,6.713) AT10(6.311,6.663) AT13(5.087,6.47) AT15(4.096,6.626) AT17(2.953,6.651) AT19(1.772,6.651) AT22(0.667,6.651) AT24(-0.667,6.651) AT27(-1.772,6.651) AT29(-2.953,6.55) AT31(-4.071,6.55) AT33(-4.985,6.499) AT36(-6.663,6.311) AU7(7.936,6.994) AU35(-6.077,7.084) AU36(-6.713,6.938) AU39(-7.991,7.141) AV6(8.237,7.645) AV11(6.068,7.396) AV13(5.087,7.232) AV15(4.096,7.388) AV17(2.953,7.413) AV19(1.772,7.413) AV22(0.667,7.413) AV24(-0.667,7.413) AV27(-1.772,7.413) AV29(-2.953,7.312) AV31(-4.071,7.312) AV33(-4.985,7.261) AW9(7.141,7.991) AW11(6.068,8.158) AW13(5.087,7.994) AW15(4.096,8.15) AW17(2.953,8.175) AW19(1.772,8.175) AW22(0.667,8.175) AW24(-0.667,8.175) AW27(-1.772,8.175) AW29(-2.953,8.074) AW31(-4.071,8.074) AW33(-5.036,8.023) AW35(-6.037,7.999) AW37(-6.994,7.936) AY5(8.764,8.585) AY38(-7.645,8.237) B1(10.814,-10.46) B2(10.33,-10.33) B3(9.824,-10.326) B43(-9.8,-10.304) B44(-10.33,-10.33) B45(-10.814,-10.46) BA40(-8.585,8.764) BB1(10.814,9.459) BB45(-10.814,9.459) BC1(10.814,9.959) BC2(10.326,9.824) BC44(-10.304,9.8) BC45(-10.814,9.959) BD1(10.814,10.46) BD2(10.33,10.33) BD3(9.8,10.304) BD43(-9.824,10.326) BD44(-10.33,10.33) BD45(-10.814,10.46) BE2(10.46,10.814) BE3(9.959,10.814) BE4(9.459,10.814) BE42(-9.459,10.814) BE43(-9.959,10.814) BE44(-10.46,10.814) C1(10.814,-9.959) C2(10.304,-9.8) C42(-9.288,-9.86) C44(-10.326,-9.824) C45(-10.814,-9.959) D1(10.814,-9.459) D45(-10.814,-9.459) F8(7.645,-8.237) G9(6.994,-7.936) G11(6.037,-7.999) G13(5.036,-8.023) G15(4.071,-8.074) G17(2.953,-8.074) G19(1.772,-8.175) G22(0.667,-8.175) G24(-0.667,-8.175) G27(-1.772,-8.175) G29(-2.953,-8.175) G31(-4.096,-8.15) G33(-5.087,-7.994) G35(-6.068,-8.158) G37(-7.141,-7.991) H13(4.985,-7.261) H15(4.071,-7.312) H17(2.953,-7.312) H19(1.772,-7.413) H22(0.667,-7.413) H24(-0.667,-7.413) H27(-1.772,-7.413) H29(-2.953,-7.413) H31(-4.096,-7.388) H33(-5.087,-7.232) H35(-6.068,-7.396) J7(7.991,-7.141) J10(6.713,-6.938) J11(6.077,-7.084) J39(-7.936,-6.994) K10(6.663,-6.311) K13(4.985,-6.499) K15(4.071,-6.55) K17(2.953,-6.55) K19(1.772,-6.651) K22(0.667,-6.651) K24(-0.667,-6.651) K27(-1.772,-6.651) K29(-2.953,-6.651) K31(-4.096,-6.626) K33(-5.087,-6.47) K36(-6.311,-6.663) K37(-6.938,-6.713) L7(8.158,-6.068) L8(7.396,-6.068) L12(5.551,-6.04) L13(5.026,-5.753) L15(4.071,-5.788) L17(2.953,-5.788) L19(1.772,-5.889) L22(0.667,-5.889) L24(-0.667,-5.889) L27(-1.772,-5.889) L29(-2.953,-5.889) L31(-4.096,-5.864) L37(-7.084,-6.077) L39(-7.999,-6.037) M35(-6.04,-5.551) N7(7.994,-5.087) N8(7.232,-5.087) N10(6.47,-5.087) N15(4.071,-5.026) N17(2.953,-5.026) N19(1.772,-5.127) N22(0.667,-5.127) N24(-0.667,-5.127) N27(-1.772,-5.127) N29(-2.953,-5.127) N31(-4.096,-5.102) N35(-5.753,-5.026) N36(-6.499,-4.985) N38(-7.261,-4.985) N39(-8.023,-5.036) P17(2.953,-4.315) P19(1.772,-4.365) P22(0.667,-4.365) P24(-0.667,-4.365) P27(-1.772,-4.365) P29(-2.953,-4.365) P31(-4.096,-4.34) R7(8.15,-4.096) R8(7.388,-4.096) R10(6.626,-4.096) R11(5.864,-4.096) R13(5.102,-4.096) R14(4.34,-4.096) R17(2.953,-3.807) R19(1.772,-3.807) R22(0.667,-3.807) R24(-0.667,-3.807) R27(-1.772,-3.807) R29(-2.953,-3.807) R33(-5.026,-4.071) R35(-5.788,-4.071) R36(-6.55,-4.071) R38(-7.312,-4.071) R39(-8.074,-4.071) U7(8.175,-2.953) U8(7.413,-2.953) U10(6.651,-2.953) U11(5.889,-2.953) U13(5.127,-2.953) U14(4.365,-2.953) U15(3.807,-2.953) U17(3.099,-3.099) U18(2.324,-3.099) U20(1.549,-3.099) U21(0.775,-3.099) U23(0,-3.099) U25(-0.775,-3.099) U26(-1.549,-3.099) U28(-2.324,-3.099) U29(-3.099,-3.099) U31(-3.807,-2.953) U32(-4.315,-2.953) U33(-5.026,-2.953) U35(-5.788,-2.953) U36(-6.55,-2.953) U38(-7.312,-2.953) U39(-8.074,-2.953) V17(3.099,-2.324) V18(2.324,-2.324) V20(1.549,-2.324) V21(0.775,-2.324) V23(0,-2.324) V25(-0.775,-2.324) V26(-1.549,-2.324) V28(-2.324,-2.324) V29(-3.099,-2.324) W7(8.175,-1.772) W8(7.413,-1.772) W10(6.651,-1.772) W11(5.889,-1.772) W13(5.127,-1.772) W14(4.365,-1.772) W15(3.807,-1.772) W31(-3.807,-1.772) W32(-4.365,-1.772) W33(-5.127,-1.772) W35(-5.889,-1.772) W36(-6.651,-1.772) W38(-7.413,-1.772) W39(-8.175,-1.772) Y17(3.099,-1.549) Y18(2.324,-1.549) Y20(1.549,-1.549) Y21(0.775,-1.549) Y23(0,-1.549) Y25(-0.775,-1.549) Y26(-1.549,-1.549) Y28(-2.324,-1.549) Y29(-3.099,-1.549)
  round 0.279 smd: A5(8.959,-10.814) A41(-8.959,-10.814) BA1(10.814,8.959) BA45(-10.814,8.959) BE5(8.959,10.814) BE41(-8.959,10.814) E1(10.814,-8.959) E45(-10.814,-8.959)
  round 0.254 smd: A6(8.458,-10.814) A40(-8.458,-10.814) AB4(9.403,-0.482) AB5(8.937,-0.667) AB41(-8.937,-0.667) AD4(9.421,0.509) AD5(8.937,0.667) AD41(-8.937,0.667) AF5(8.885,1.721) AF41(-8.887,1.721) AG4(9.403,1.791) AJ5(8.836,2.953) AJ41(-8.937,2.953) AL4(9.403,4.064) AL5(8.836,4.071) AL41(-8.887,4.096) AN4(9.421,5.056) AN5(8.785,5.163) AN41(-8.756,5.087) AR5(8.886,6.182) AR41(-8.92,6.068) AU41(-9.038,7.09) AV4(9.229,7.321) AW4(9.434,8.204) AW42(-9.24,7.816) AY1(10.814,8.458) AY45(-10.814,8.458) B6(8.45,-10.296) B25(-1.225,-10.306) B40(-8.701,-10.355) BA4(9.602,9.12) BA5(8.767,9.095) BA9(7.09,9.038) BA11(6.068,8.92) BA13(5.087,8.756) BA15(4.096,8.887) BA17(2.953,8.937) BA20(1.721,8.887) BA22(0.667,8.937) BA24(-0.667,8.937) BA26(-1.721,8.885) BA29(-2.953,8.836) BA31(-4.071,8.836) BA33(-5.163,8.785) BA35(-6.182,8.886) BA41(-9.095,8.767) BB3(10.162,9.344) BB7(7.816,9.24) BB38(-7.321,9.229) BB39(-8.204,9.434) BB41(-9.12,9.602) BB43(-9.86,9.288) BC4(9.288,9.86) BC42(-9.344,10.162) BE6(8.458,10.814) BE40(-8.458,10.814) C10(6.724,-9.727) C28(-2.369,-9.727) C37(-6.915,-9.727) D3(9.86,-9.288) D5(9.12,-9.602) D7(8.204,-9.434) D8(7.321,-9.229) D10(6.338,-9.403) D15(4.064,-9.403) D17(2.783,-9.421) D19(1.791,-9.403) D24(-0.482,-9.403) D27(-1.764,-9.421) D29(-2.756,-9.403) D31(-4.037,-9.421) D33(-5.029,-9.403) D36(-6.311,-9.421) D39(-7.816,-9.24) D43(-10.162,-9.344) E5(9.095,-8.767) E6(8.585,-8.764) E11(6.182,-8.886) E13(5.163,-8.785) E15(4.071,-8.836) E17(2.953,-8.836) E20(1.721,-8.885) E22(0.667,-8.937) E24(-0.667,-8.937) E26(-1.721,-8.887) E29(-2.953,-8.937) E31(-4.096,-8.887) E33(-5.087,-8.756) E35(-6.068,-8.92) E37(-7.09,-9.038) E41(-8.767,-9.095) E42(-9.602,-9.12) F1(10.814,-8.458) F41(-8.764,-8.585) F44(-10.296,-8.45) F45(-10.814,-8.458) G4(9.24,-7.816) G42(-9.434,-8.204) H3(9.888,-7.391) H40(-8.237,-7.645) H42(-9.229,-7.321) J3(9.727,-6.915) J5(9.038,-7.09) K4(9.421,-6.311) K42(-9.403,-6.338) K43(-9.727,-6.724) L5(8.92,-6.068) L41(-8.886,-6.182) N4(9.403,-5.029) N5(8.756,-5.087) N41(-8.785,-5.163) R5(8.887,-4.096) R41(-8.836,-4.071) U4(9.403,-2.756) U5(8.937,-2.953) U41(-8.836,-2.953) V3(9.727,-2.369) W4(9.421,-1.764) Y5(8.887,-1.721) Y41(-8.885,-1.721)
  oval 0.203x0.254 smd: A7(7.893,-10.814) A9(6.852,-10.814) A37(-6.839,-10.814) A39(-7.893,-10.814) B7(7.944,-10.306) B39(-7.944,-10.306) BD6(8.701,10.355) BD7(7.944,10.306) BD39(-7.944,10.306) BE7(7.893,10.814) BE9(6.839,10.814) BE37(-6.852,10.814) BE39(-7.893,10.814)
  oval 0.152x0.254 smd: A12(5.595,-10.814) A14(4.553,-10.814) A16(3.321,-10.814) A18(2.28,-10.814) A21(1.048,-10.814) A23(0.007,-10.814) A25(-1.225,-10.814) A28(-2.267,-10.814) A30(-3.499,-10.814) A32(-4.54,-10.814) A35(-5.772,-10.814) AA4(9.326,-1.225) AA42(-9.324,-1.048) AE4(9.324,1.048) AE42(-9.326,1.225) AK4(9.324,3.321) AK42(-9.326,3.499) AP4(9.324,5.595) AR42(-9.326,5.772) B8(7.258,-10.428) B10(6.724,-10.235) B11(6.211,-10.396) B12(5.595,-10.306) B13(4.934,-10.428) B14(4.451,-10.235) B15(3.937,-10.396) B16(3.321,-10.306) B18(2.661,-10.428) B19(2.178,-10.235) B20(1.664,-10.396) B21(1.048,-10.306) B22(0.388,-10.428) B23(-0.096,-10.235) B24(-0.609,-10.396) B27(-1.886,-10.428) B28(-2.369,-10.235) B29(-2.883,-10.396) B30(-3.499,-10.306) B31(-4.159,-10.428) B32(-4.642,-10.235) B33(-5.156,-10.396) B35(-5.772,-10.306) B36(-6.432,-10.428) B37(-6.915,-10.235) B38(-7.391,-10.396) BB10(6.311,9.421) BB13(5.029,9.403) BB15(4.037,9.421) BB17(2.756,9.403) BB19(1.764,9.421) BB22(0.482,9.403) BB24(-0.509,9.421) BB27(-1.791,9.403) BB29(-2.783,9.421) BB31(-4.064,9.403) BB33(-5.056,9.421) BB36(-6.338,9.403) BC8(7.391,9.888) BC9(6.915,9.727) BC10(6.336,9.929) BC13(5.156,9.888) BC14(4.642,9.727) BC15(4.063,9.929) BC17(2.883,9.888) BC18(2.369,9.727) BC19(1.789,9.929) BC22(0.609,9.888) BC23(0.096,9.727) BC24(-0.484,9.929) BC26(-1.664,9.888) BC27(-2.178,9.727) BC29(-2.757,9.929) BC31(-3.937,9.888) BC32(-4.451,9.727) BC33(-5.03,9.929) BC35(-6.211,9.888) BC36(-6.724,9.727) BC38(-7.355,9.929) BD8(7.391,10.396) BD9(6.915,10.235) BD10(6.432,10.428) BD11(5.772,10.306) BD13(5.156,10.396) BD14(4.642,10.235) BD15(4.159,10.428) BD16(3.499,10.306) BD17(2.883,10.396) BD18(2.369,10.235) BD19(1.886,10.428) BD21(1.225,10.306) BD22(0.609,10.396) BD23(0.096,10.235) BD24(-0.388,10.428) BD25(-1.048,10.306) BD26(-1.664,10.396) BD27(-2.178,10.235) BD28(-2.661,10.428) BD30(-3.321,10.306) BD31(-3.937,10.396) BD32(-4.451,10.235) BD33(-4.934,10.428) BD34(-5.595,10.306) BD35(-6.211,10.396) BD36(-6.724,10.235) BD38(-7.258,10.428) BE11(5.772,10.814) BE14(4.54,10.814) BE16(3.499,10.814) BE18(2.267,10.814) BE21(1.225,10.814) BE23(-0.007,10.814) BE25(-1.048,10.814) BE28(-2.28,10.814) BE30(-3.321,10.814) BE32(-4.553,10.814) BE34(-5.595,10.814) C8(7.355,-9.929) C11(6.211,-9.888) C13(5.03,-9.929) C14(4.451,-9.727) C15(3.937,-9.888) C17(2.757,-9.929) C19(2.178,-9.727) C20(1.664,-9.888) C22(0.484,-9.929) C23(-0.096,-9.727) C24(-0.609,-9.888) C27(-1.789,-9.929) C29(-2.883,-9.888) C31(-4.063,-9.929) C32(-4.642,-9.727) C33(-5.156,-9.888) C36(-6.336,-9.929) C38(-7.391,-9.888) D13(5.056,-9.421) D22(0.509,-9.421) L4(9.326,-5.772) M42(-9.324,-5.595) T4(9.326,-3.499) T42(-9.324,-3.321)
  oval 0.254x0.152 smd: AA1(10.814,-1.225) AA2(10.306,-1.225) AA44(-10.306,-1.048) AA45(-10.814,-1.048) AB2(10.396,-0.609) AB3(9.888,-0.609) AB42(-9.421,-0.509) AB43(-9.929,-0.484) AB44(-10.428,-0.388) AC1(10.814,0.007) AC2(10.235,-0.096) AC3(9.727,-0.096) AC43(-9.727,0.096) AC44(-10.235,0.096) AC45(-10.814,-0.007) AD2(10.428,0.388) AD3(9.929,0.484) AD42(-9.403,0.482) AD43(-9.888,0.609) AD44(-10.396,0.609) AE1(10.814,1.048) AE2(10.306,1.048) AE44(-10.306,1.225) AE45(-10.814,1.225) AF2(10.396,1.664) AF3(9.888,1.664) AG2(10.235,2.178) AG3(9.727,2.178) AG42(-9.421,1.764) AG43(-9.929,1.789) AG44(-10.428,1.886) AH1(10.814,2.28) AH2(10.428,2.661) AH43(-9.727,2.369) AH44(-10.235,2.369) AH45(-10.814,2.267) AJ3(9.929,2.757) AJ4(9.421,2.783) AJ42(-9.403,2.756) AJ43(-9.888,2.883) AJ44(-10.396,2.883) AK1(10.814,3.321) AK2(10.306,3.321) AK44(-10.306,3.499) AK45(-10.814,3.499) AL2(10.396,3.937) AL3(9.888,3.937) AL42(-9.421,4.037) AL43(-9.929,4.063) AL44(-10.428,4.159) AM1(10.814,4.553) AM2(10.235,4.451) AM3(9.727,4.451) AM43(-9.727,4.642) AM44(-10.235,4.642) AM45(-10.814,4.54) AN2(10.428,4.934) AN3(9.929,5.03) AN42(-9.403,5.029) AN43(-9.888,5.156) AN44(-10.396,5.156) AP1(10.814,5.595) AP2(10.306,5.595) AR2(10.396,6.211) AR3(9.888,6.211) AR44(-10.306,5.772) AR45(-10.814,5.772) AT2(10.235,6.724) AT3(9.727,6.724) AT4(9.403,6.338) AT42(-9.421,6.311) AT43(-9.929,6.336) AT44(-10.428,6.432) AU43(-9.727,6.915) AU44(-10.235,6.915) AV2(10.428,7.258) AV3(9.929,7.355) AV43(-9.888,7.391) AV44(-10.396,7.391) BB11(5.772,9.326) BB16(3.499,9.326) BB21(1.225,9.326) BB25(-1.048,9.324) BB30(-3.321,9.324) BB34(-5.595,9.324) D12(5.595,-9.324) D16(3.321,-9.324) D21(1.048,-9.324) D25(-1.225,-9.326) D30(-3.499,-9.326) D35(-5.772,-9.326) H2(10.396,-7.391) H43(-9.929,-7.355) H44(-10.428,-7.258) J2(10.235,-6.915) K2(10.428,-6.432) K3(9.929,-6.336) K44(-10.235,-6.724) L1(10.814,-5.772) L2(10.306,-5.772) L43(-9.888,-6.211) L44(-10.396,-6.211) M44(-10.306,-5.595) M45(-10.814,-5.595) N2(10.396,-5.156) N3(9.888,-5.156) N42(-9.421,-5.056) N43(-9.929,-5.03) N44(-10.428,-4.934) P1(10.814,-4.54) P2(10.235,-4.642) P3(9.727,-4.642) P43(-9.727,-4.451) P44(-10.235,-4.451) P45(-10.814,-4.553) R2(10.428,-4.159) R3(9.929,-4.063) R4(9.421,-4.037) R42(-9.403,-4.064) R43(-9.888,-3.937) R44(-10.396,-3.937) T1(10.814,-3.499) T2(10.306,-3.499) T44(-10.306,-3.321) T45(-10.814,-3.321) U2(10.396,-2.883) U3(9.888,-2.883) U42(-9.421,-2.783) U43(-9.929,-2.757) V1(10.814,-2.267) V2(10.235,-2.369) V44(-10.428,-2.661) V45(-10.814,-2.28) W2(10.428,-1.886) W3(9.929,-1.789) W42(-9.403,-1.791) W43(-9.727,-2.178) W44(-10.235,-2.178) Y43(-9.888,-1.664) Y44(-10.396,-1.664)
  oval 0.254x0.203 smd: AU1(10.814,6.852) AU45(-10.814,6.839) AW1(10.814,7.893) AW2(10.306,7.944) AW44(-10.306,7.944) AW45(-10.814,7.893) AY44(-10.355,8.701) F2(10.355,-8.701) G1(10.814,-7.893) G2(10.306,-7.944) G44(-10.306,-7.944) G45(-10.814,-7.893) J1(10.814,-6.839) J45(-10.814,-6.852)
  round 0.368 smd: AY2(10.296,8.45) BD40(-8.45,10.296) C4(9.344,-10.162)
C402H22
  custom 0.152x0.152 smd: 1(0,0.445) 2(0,-0.445)
C603
  custom 0.216x0.216 smd: 1(0,0.762) 2(0,-0.762)
C603H36
  custom 0.216x0.216 smd: 1(0,0.762) 2(0,-0.762)
C603H38
  custom 0.216x0.216 smd: 1(0,0.762) 2(0,-0.762)
C603H40
  custom 0.216x0.216 smd: 1(0,0.762) 2(0,-0.762)
C805H50
  rect 1.397x1.143 smd: 1(0,0.965) 2(0,-0.965)
C805H54
  rect 1.397x1.143 smd: 1(0,0.965) 2(0,-0.965)
C805H56
  rect 1.397x1.143 smd: 1(0,0.965) 2(0,-0.965)
C805H58
  rect 1.397x1.143 smd: 1(0,0.965) 2(0,-0.965)
C1206H71
  rect 1.651x1.27 smd: 1(0,1.397) 2(0,-1.397)
C4201WV0-2-2P
  round 2.184 hole 1.422: 1(-2.1,2.75) 2(2.1,2.75) 3(-2.1,-2.75) 4(2.1,-2.75)
C4201WV0-B2X12P
  round 2.184 hole 1.422: 1(-23.1,2.75) 2(-18.9,2.75) 3(-14.7,2.75) 4(-10.5,2.75) 5(-6.3,2.75) 6(-2.1,2.75) 7(2.1,2.75) 8(6.3,2.75) 9(10.5,2.75) 10(14.7,2.75) 11(18.9,2.75) 12(23.1,2.75) 13(-23.1,-2.75) 14(-18.9,-2.75) 15(-14.7,-2.75) 16(-10.5,-2.75) 17(-6.3,-2.75) 18(-2.1,-2.75) 19(2.1,-2.75) 20(6.3,-2.75) 21(10.5,-2.75) 22(14.7,-2.75) 23(18.9,-2.75) 24(23.1,-2.75)
CON2C-U
  custom 0.171x0.171 smd: 1(0,0.533) 2(0,-0.533)
CT3528H48
  rect 2.286x2.286 smd: 1(0,1.905) 2(0,-1.905)
D1608AK-UH28
  rect 0.559x0.711 smd: A(0,0.889) K(0,-0.889)
D5126145AKH91
  rect 1.702x2.032 smd: A(0,2.172) K(0,-2.172)
DFN8F3-G2416H32
  rect 0.356x0.991 smd: 1(0.975,1.513) 2(0.325,1.513) 3(-0.325,1.513) 4(-0.975,1.513) 5(-0.975,-1.513) 6(-0.325,-1.513) 7(0.325,-1.513) 8(0.975,-1.513)
  rect 2.362x1.6 smd: 9(0,0)
DFN10G3-G265175H32
  rect 0.305x0.914 smd: 1(1,1.549) 2(0.5,1.549) 3(0,1.549) 4(-0.5,1.549) 5(-1,1.549) 6(-1,-1.549) 7(-0.5,-1.549) 8(0,-1.549) 9(0.5,-1.549) 10(1,-1.549)
  rect 2.642x1.753 smd: 11(0,0)
DFN10G2510H26
  rect 0.305x0.787 smd: 1(1,0.494) 5(-1,0.494) 6(-1,-0.494) 10(1,-0.494)
  rect 0.254x0.787 smd: 2(0.521,0.494) 4(-0.521,0.494) 7(-0.521,-0.494) 9(0.521,-0.494)
  rect 0.025x0.025 smd: 3(0,0.494)
  rect 0.406x1.753 smd: 8(0,-0.494)
DM-BSH-03001-FDA-01
  round 0.254 hole 1.016 unplated: (-10.065,0) (10.065,0)
  rect 0.279x2.769 smd: 1(-7.25,-5.526) 2(-7.25,0.198) 3(-6.75,-5.526) 4(-6.75,0.198) 5(-6.25,-5.526) 6(-6.25,0.198) 7(-5.751,-5.526) 8(-5.751,0.198) 9(-5.25,-5.526) 10(-5.25,0.198) 11(-4.75,-5.526) 12(-4.75,0.198) 13(-4.249,-5.526) 14(-4.249,0.198) 15(-3.75,-5.526) 16(-3.75,0.198) 17(-3.25,-5.526) 18(-3.25,0.198) 19(-2.75,-5.526) 20(-2.75,0.198) 21(-2.25,-5.526) 22(-2.25,0.198) 23(-1.75,-5.526) 24(-1.75,0.198) 25(-1.25,-5.526) 26(-1.25,0.198) 27(-0.751,-5.526) 28(-0.751,0.198) 29(-0.25,-5.526) 30(-0.25,0.198) 31(0.25,-5.526) 32(0.25,0.198) 33(0.751,-5.526) 34(0.751,0.198) 35(1.25,-5.526) 36(1.25,0.198) 37(1.75,-5.526) 38(1.75,0.198) 39(2.25,-5.526) 40(2.25,0.198) 41(2.75,-5.526) 42(2.75,0.198) 43(3.25,-5.526) 44(3.25,0.198) 45(3.75,-5.526) 46(3.75,0.198) 47(4.249,-5.526) 48(4.249,0.198) 49(4.75,-5.526) 50(4.75,0.198) 51(5.25,-5.526) 52(5.25,0.198) 53(5.751,-5.526) 54(5.751,0.198) 55(6.25,-5.526) 56(6.25,0.198) 57(6.75,-5.526) 58(6.75,0.198) 59(7.25,-5.526) 60(7.25,0.198)
ECAP-100D5H573
  rect 1.397x1.397 hole 0.991: 1(0,-1.27)
  round 1.397 hole 0.991: 2(0,1.27)
ECAP-100D6D3H355
  rect 1.397x1.397 hole 0.991: 1(0,-1.27)
  round 1.397 hole 0.991: 2(0,1.27)
ECAP-100D6D3H473
  rect 1.397x1.397 hole 0.991: 1(0,-1.27)
  round 1.397 hole 0.991: 2(0,1.27)
ECAP-138D8-UH355
  rect 1.397x1.397 hole 0.991: 1(0,-1.75)
  round 1.397 hole 0.991: 2(0,1.75)
GAP-CLOSE-PWR-3
  rect 0.66x0.762 smd: 1(-0.305,0) 2(0.305,0)
GAP-OPEN-PWR-2
  custom 0.191x0.191 smd: 1(0,0.47) 2(0,-0.47)
GENS315R158-8-F-A
  round 0.254 hole 4.013 unplated: (0,0)
  round 0.864 hole 0.508: 1(-0.634,3.189) 2(-2.703,1.806) 3(-3.189,-0.634) 4(-1.806,-2.703) 5(0.634,-3.189) 6(2.703,-1.806) 7(3.189,0.634) 8(1.806,2.703)
HF1004E
  round 1.549 hole 1.143: 1(3.81,0) 2(1.27,0) 3(-1.27,0) 4(-3.81,0)
HY-11H394
  round 1.778 hole 0.991: 1(-3.251,0) 2(3.251,0)
L603H38
  custom 0.216x0.216 smd: 1(0,0.762) 2(0,-0.762)
L1608-UH38
  custom 0.216x0.216 smd: 1(0,0.762) 2(0,-0.762)
L20125H44
  rect 1.397x1.143 smd: 1(0,0.965) 2(0,-0.965)
L112100-2135H158
  rect 4.013x3.251 smd: 1(0,4.72) 2(0,-4.72)
L125100-4P-1H37
  rect 0.762x0.432 smd: 1(0.625,0.341) 2(-0.625,0.341) 3(-0.625,-0.341) 4(0.625,-0.341)
L125100-4P-4H28
  rect 0.762x0.432 smd: 1(-0.625,0.341) 2(0.625,0.341) 3(0.625,-0.341) 4(-0.625,-0.341)
L125100-4P-5H24
  rect 0.457x0.838 smd: 1(-0.326,0.587) 2(0.326,0.587) 3(-0.326,-0.587) 4(0.326,-0.587)
L125100-4PH24
  rect 0.457x0.838 smd: 1(-0.326,-0.587) 2(0.326,-0.587) 3(0.326,0.587) 4(-0.326,0.587)
L125100-4PH26
  rect 0.457x0.838 smd: 1(-0.326,-0.587) 2(0.326,-0.587) 3(0.326,0.587) 4(-0.326,0.587)
L686647-127318H119
  rect 3.683x2.413 smd: 1(0,2.986) 2(0,-2.986)
L35301330H103
  rect 3.251x1.93 smd: 1(0,1.161) 2(0,-1.161)
LQFP48H63
  rect 0.305x1.524 smd: 1(2.75,4.242) 2(2.25,4.242) 3(1.75,4.242) 4(1.25,4.242) 5(0.751,4.242) 6(0.25,4.242) 7(-0.25,4.242) 8(-0.751,4.242) 9(-1.25,4.242) 10(-1.75,4.242) 11(-2.25,4.242) 12(-2.75,4.242) 25(-2.75,-4.242) 26(-2.25,-4.242) 27(-1.75,-4.242) 28(-1.25,-4.242) 29(-0.751,-4.242) 30(-0.25,-4.242) 31(0.25,-4.242) 32(0.751,-4.242) 33(1.25,-4.242) 34(1.75,-4.242) 35(2.25,-4.242) 36(2.75,-4.242)
  rect 1.524x0.305 smd: 13(-4.242,2.75) 14(-4.242,2.25) 15(-4.242,1.75) 16(-4.242,1.25) 17(-4.242,0.751) 18(-4.242,0.25) 19(-4.242,-0.25) 20(-4.242,-0.751) 21(-4.242,-1.25) 22(-4.242,-1.75) 23(-4.242,-2.25) 24(-4.242,-2.75) 37(4.242,-2.75) 38(4.242,-2.25) 39(4.242,-1.75) 40(4.242,-1.25) 41(4.242,-0.751) 42(4.242,-0.25) 43(4.242,0.25) 44(4.242,0.751) 45(4.242,1.25) 46(4.242,1.75) 47(4.242,2.25) 48(4.242,2.75)
NTC-402H22-U
  custom 0.14x0.14 smd: 1(0,0.445) 2(0,-0.445)
NTC-402H24-U
  custom 0.14x0.14 smd: 1(0,0.445) 2(0,-0.445)
OSC-3225-4P-4H36
  rect 1.397x1.067 smd: 1(-1.171,-0.756) 2(1.171,-0.756) 3(1.171,0.756) 4(-1.171,0.756)
P125-2204P-A1BS-025-U
  round 1.422 hole 1.016: 1(-3.81,-1.27) 2(-3.81,1.27) 3(-1.27,-1.27) 5(1.27,-1.27) 6(1.27,1.27) 7(3.81,-1.27) 8(3.81,1.27)
  rect 0.025x0.025 smd: 4(-1.27,1.27)
POLYSW-3217-UH40
  rect 1.905x1.143 smd: 1(0,1.418) 2(0,-1.418)
PPAK-8PH48
  rect 0.762x1.524 smd: 1(-1.905,-3.81) 2(-0.635,-3.81) 3(0.635,-3.81) 4(1.905,-3.81)
  rect 5.283x5.08 smd: 5(0,0)
  rect 0.025x0.025 smd: 6(0.635,2.032) 7(-0.635,2.032) 8(-1.905,2.032)
PQFP128H134
  rect 0.305x1.778 smd: 1(9.249,8.217) 2(8.75,8.217) 3(8.25,8.217) 4(7.75,8.217) 5(7.25,8.217) 6(6.75,8.217) 7(6.25,8.217) 8(5.751,8.217) 9(5.25,8.217) 10(4.75,8.217) 11(4.249,8.217) 12(3.75,8.217) 13(3.25,8.217) 14(2.75,8.217) 15(2.25,8.217) 16(1.75,8.217) 17(1.25,8.217) 18(0.751,8.217) 19(0.25,8.217) 20(-0.25,8.217) 21(-0.751,8.217) 22(-1.25,8.217) 23(-1.75,8.217) 24(-2.25,8.217) 25(-2.75,8.217) 26(-3.25,8.217) 27(-3.75,8.217) 28(-4.249,8.217) 29(-4.75,8.217) 30(-5.25,8.217) 31(-5.751,8.217) 32(-6.25,8.217) 33(-6.75,8.217) 34(-7.25,8.217) 35(-7.75,8.217) 36(-8.25,8.217) 37(-8.75,8.217) 38(-9.249,8.217) 65(-9.249,-8.217) 66(-8.75,-8.217) 67(-8.25,-8.217) 68(-7.75,-8.217) 69(-7.25,-8.217) 70(-6.75,-8.217) 71(-6.25,-8.217) 72(-5.751,-8.217) 73(-5.25,-8.217) 74(-4.75,-8.217) 75(-4.249,-8.217) 76(-3.75,-8.217) 77(-3.25,-8.217) 78(-2.75,-8.217) 79(-2.25,-8.217) 80(-1.75,-8.217) 81(-1.25,-8.217) 82(-0.751,-8.217) 83(-0.25,-8.217) 84(0.25,-8.217) 85(0.751,-8.217) 86(1.25,-8.217) 87(1.75,-8.217) 88(2.25,-8.217) 89(2.75,-8.217) 90(3.25,-8.217) 91(3.75,-8.217) 92(4.249,-8.217) 93(4.75,-8.217) 94(5.25,-8.217) 95(5.751,-8.217) 96(6.25,-8.217) 97(6.75,-8.217) 98(7.25,-8.217) 99(7.75,-8.217) 100(8.25,-8.217) 101(8.75,-8.217) 102(9.249,-8.217)
  rect 1.778x0.305 smd: 39(-11.214,6.25) 40(-11.214,5.751) 41(-11.214,5.25) 42(-11.214,4.75) 43(-11.214,4.249) 44(-11.214,3.75) 45(-11.214,3.25) 46(-11.214,2.75) 47(-11.214,2.25) 48(-11.214,1.75) 49(-11.214,1.25) 50(-11.214,0.751) 51(-11.214,0.25) 52(-11.214,-0.25) 53(-11.214,-0.751) 54(-11.214,-1.25) 55(-11.214,-1.75) 56(-11.214,-2.25) 57(-11.214,-2.75) 58(-11.214,-3.25) 59(-11.214,-3.75) 60(-11.214,-4.249) 61(-11.214,-4.75) 62(-11.214,-5.25) 63(-11.214,-5.751) 64(-11.214,-6.25) 103(11.214,-6.25) 104(11.214,-5.751) 105(11.214,-5.25) 106(11.214,-4.75) 107(11.214,-4.249) 108(11.214,-3.75) 109(11.214,-3.25) 110(11.214,-2.75) 111(11.214,-2.25) 112(11.214,-1.75) 113(11.214,-1.25) 114(11.214,-0.751) 115(11.214,-0.25) 116(11.214,0.25) 117(11.214,0.751) 118(11.214,1.25) 119(11.214,1.75) 120(11.214,2.25) 121(11.214,2.75) 122(11.214,3.25) 123(11.214,3.75) 124(11.214,4.249) 125(11.214,4.75) 126(11.214,5.25) 127(11.214,5.751) 128(11.214,6.25)
QFN12J1D6H24
  rect 0.203x0.66 smd: 1(0.6,0.851) 2(0.2,0.851) 3(-0.2,0.851) 4(-0.6,0.851) 7(-0.6,-0.851) 8(-0.2,-0.851) 9(0.2,-0.851) 10(0.6,-0.851)
  rect 0.66x0.203 smd: 5(-0.851,0.2) 6(-0.851,-0.2) 11(0.851,-0.2) 12(0.851,0.2)
QFN16-G1D8-UH32
  rect 0.305x0.914 smd: 1(0.75,1.551) 2(0.25,1.551) 3(-0.25,1.551) 4(-0.75,1.551) 9(-0.75,-1.551) 10(-0.25,-1.551) 11(0.25,-1.551) 12(0.75,-1.551)
  rect 0.914x0.305 smd: 5(-1.551,0.75) 6(-1.551,0.25) 7(-1.551,-0.25) 8(-1.551,-0.75) 13(1.551,-0.75) 14(1.551,-0.25) 15(1.551,0.25) 16(1.551,0.75)
  rect 1.778x1.778 smd: 17(0,0)
QFN16G3-G1D85-UH40
  rect 0.305x0.508 smd: 1(0.75,1.397) 2(0.25,1.397) 3(-0.25,1.397) 4(-0.75,1.397) 9(-0.75,-1.397) 10(-0.25,-1.397) 11(0.25,-1.397) 12(0.75,-1.397)
  rect 0.508x0.305 smd: 5(-1.397,0.75) 6(-1.397,0.25) 7(-1.397,-0.25) 8(-1.397,-0.75) 13(1.397,-0.75) 14(1.397,-0.25) 15(1.397,0.25) 16(1.397,0.75)
  rect 1.702x1.702 smd: 17(0,0)
QFN20-G1D75H32
  rect 0.203x0.914 smd: 1(0.8,1.551) 2(0.4,1.551) 3(0,1.551) 4(-0.4,1.551) 5(-0.8,1.551) 11(-0.8,-1.551) 12(-0.4,-1.551) 13(0,-1.551) 14(0.4,-1.551) 15(0.8,-1.551)
  rect 0.914x0.203 smd: 6(-1.551,0.8) 7(-1.551,0.4) 8(-1.551,0) 9(-1.551,-0.4) 10(-1.551,-0.8) 16(1.551,-0.8) 17(1.551,-0.4) 18(1.551,0) 19(1.551,0.4) 20(1.551,0.8)
  rect 1.753x1.753 smd: 21(0,0)
QFN32J4-G2D85H36
  rect 0.203x0.864 smd: 1(1.4,2.085) 2(1,2.085) 3(0.6,2.085) 4(0.2,2.085) 5(-0.2,2.085) 6(-0.6,2.085) 7(-1,2.085) 8(-1.4,2.085) 17(-1.4,-2.085) 18(-1,-2.085) 19(-0.6,-2.085) 20(-0.2,-2.085) 21(0.2,-2.085) 22(0.6,-2.085) 23(1,-2.085) 24(1.4,-2.085)
  rect 0.864x0.203 smd: 9(-2.085,1.4) 10(-2.085,1) 11(-2.085,0.6) 12(-2.085,0.2) 13(-2.085,-0.2) 14(-2.085,-0.6) 15(-2.085,-1) 16(-2.085,-1.4) 25(2.085,-1.4) 26(2.085,-1) 27(2.085,-0.6) 28(2.085,-0.2) 29(2.085,0.2) 30(2.085,0.6) 31(2.085,1) 32(2.085,1.4)
  rect 2.845x2.845 smd: 33(0,0)
R402H14
  custom 0.14x0.14 smd: 1(0,0.445) 2(0,-0.445)
R402H16
  custom 0.14x0.14 smd: 1(0,0.445) 2(0,-0.445)
R603H22
  custom 0.216x0.216 smd: 1(0,0.762) 2(0,-0.762)
R805H24
  rect 1.397x1.143 smd: 1(0,0.965) 2(0,-0.965)
R1206H28
  rect 1.651x1.27 smd: 1(0,1.397) 2(0,-1.397)
RT-D6-4D5-1010H375
  round 2.489 hole 1.727: 1(3,2.25) 2(-3,-2.25)
RT-D6D2-108108H426
  round 2.286 hole 1.524: 1(3.1,3.1) 2(-3.1,-3.1)
RU1-AQ1K9WGF
  round 2.718 hole 2.311: G1(9.35,0) G2(-9.35,0) G3(6.57,-4.37) G4(-6.57,-4.37) G5(6.57,-10.05) G6(-6.57,-10.05) G7(9.35,-12.68) G8(-9.35,-12.68)
  round 1.321 hole 0.914: L1(7.2,5.47) L2(4.66,5.47) L3(-4.66,5.47) L4(-7.2,5.47) R1(5.715,0.1) R2(4.445,2.64) R3(3.175,0.1) R4(1.905,2.64) R5(0.635,0.1) R6(-0.635,2.64) R7(-1.905,0.1) R8(-3.175,2.64) R9(-4.445,0.1) R10(-5.715,2.64)
  round 1.346 hole 0.94: U1(-3.5,-7.339) U2(-0.999,-7.339) U3(0.999,-7.339) U4(3.5,-7.339) U5(-3.5,-4.719) U6(-0.999,-4.719) U7(0.999,-4.719) U8(3.5,-4.719)
SC70-5H44
  rect 0.406x1.219 smd: 1(0.65,0.826) 2(0,0.826) 3(-0.65,0.826) 4(-0.65,-0.826) 5(0.65,-0.826)
SC70-6H48
  rect 0.406x1.016 smd: 1(-0.65,-0.94) 2(0,-0.94) 3(0.65,-0.94) 4(0.65,0.94) 5(0,0.94) 6(-0.65,0.94)
SKT-HDMI23-150122-10
  rect 0.305x2.591 smd: 1(4.5,6.725) 2(4,6.725) 3(3.5,6.725) 4(3,6.725) 5(2.501,6.725) 6(2,6.725) 7(1.5,6.725) 8(0.999,6.725) 9(0.5,6.725) 10(0,6.725) 11(-0.5,6.725) 12(-0.999,6.725) 13(-1.5,6.725) 14(-2,6.725) 15(-2.501,6.725) 16(-3,6.725) 17(-3.5,6.725) 18(-4,6.725) 19(-4.5,6.725)
  oval 1.626x3.429 hole 0.914x2.718: 20(7.25,5.96) 22(-7.25,5.96)
  oval 1.626x2.819 hole 0.914x2.108: 21(7.25,0) 23(-7.25,0)
SKT-SOIC8-092117H235
  rect 0.508x1.702 smd: 1(1.905,4.1) 2(0.635,4.1) 3(-0.635,4.1) 4(-1.905,4.1) 5(-1.905,-4.1) 6(-0.635,-4.1) 7(0.635,-4.1) 8(1.905,-4.1)
SKT-USB22-156174
  round 1.067 hole 0.711: 1(-3.5,2) 2(-1,2) 3(1,2) 4(3.5,2) 5(4,3.5) 6(2,3.5) 7(0,3.5) 8(-2,3.5) 9(-4,3.5) 10(-3.5,5.2) 11(-1,5.2) 12(1,5.2) 13(3.5,5.2) 14(4,6.7) 15(2,6.7) 16(0,6.7) 17(-2,6.7) 18(-4,6.7)
  round 2.718 hole 2.311: 19(-6.57,0) 20(6.57,0) 21(-6.57,5.68) 22(6.57,5.68)
